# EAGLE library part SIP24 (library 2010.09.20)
Single In Line Modified to resemble Game Gear card edge connector. Pins would ideally be 0.15" long and not have holes in them. Pads will be replaced with polygons once dimensions have been verified. Drawn by Darren Lue Choy &micro; 2010.09.21
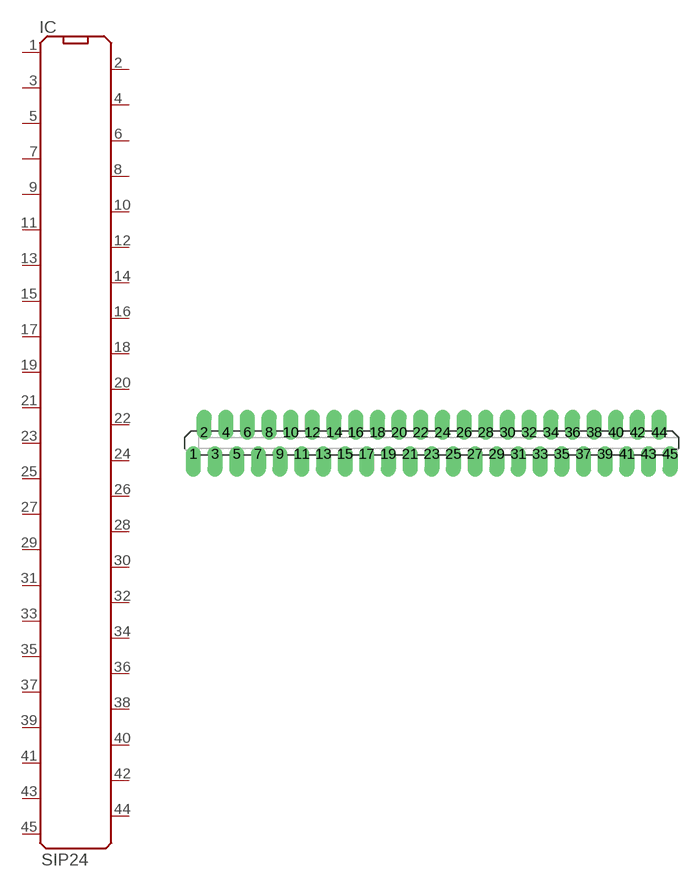
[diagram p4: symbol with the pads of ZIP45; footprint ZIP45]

Designator prefix IC

## SIP24  [ZIP45]
1  1  pas
2  2  pas
3  3  pas
4  4  pas
5  5  pas
6  6  pas
7  7  pas
8  8  pas
9  9  pas
10  10  pas
11  11  pas
12  12  pas
13  13  pas
14  14  pas
15  15  pas
16  16  pas
17  17  pas
18  18  pas
19  19  pas
20  20  pas
21  21  pas
22  22  pas
23  23  pas
24  24  pas
25  25  pas
26  26  pas
27  27  pas
28  28  pas
29  29  pas
30  30  pas
31  31  pas
32  32  pas
33  33  pas
34  34  pas
35  35  pas
36  36  pas
37  37  pas
38  38  pas
39  39  pas
40  40  pas
41  41  pas
42  42  pas
43  43  pas
44  44  pas
45  45  pas

## Footprint ZIP45 (pad centres in mm)
Single In Line Socket Modified to resemble the Game Gear cardedge connector. The pads would ideally be 0.2" long, and not have holes. When the pin spacings have been confirmed this will be redrawn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
drill 0.5 pad 1.778 offset: 1 -27.94,-1.27; 2 -26.67,1.27; 3 -25.4,-1.27; 4 -24.13,1.27; 5 -22.86,-1.27; 6 -21.59,1.27; 7 -20.32,-1.27; 8 -19.05,1.27; 9 -17.78,-1.27; 10 -16.51,1.27; 11 -15.24,-1.27; 12 -13.97,1.27; 13 -12.7,-1.27; 14 -11.43,1.27; 15 -10.16,-1.27; 16 -8.89,1.27; 17 -7.62,-1.27; 18 -6.35,1.27; 19 -5.08,-1.27; 20 -3.81,1.27; 21 -2.54,-1.27; 22 -1.27,1.27; 23 0,-1.27; 24 1.27,1.27; 25 2.54,-1.27; 26 3.81,1.27; 27 5.08,-1.27; 28 6.35,1.27; 29 7.62,-1.27; 30 8.89,1.27; 31 10.16,-1.27; 32 11.43,1.27; 33 12.7,-1.27; 34 13.97,1.27; 35 15.24,-1.27; 36 16.51,1.27; 37 17.78,-1.27; 38 19.05,1.27; 39 20.32,-1.27; 40 21.59,1.27; 41 22.86,-1.27; 42 24.13,1.27; 43 25.4,-1.27; 44 26.67,1.27; 45 27.94,-1.27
